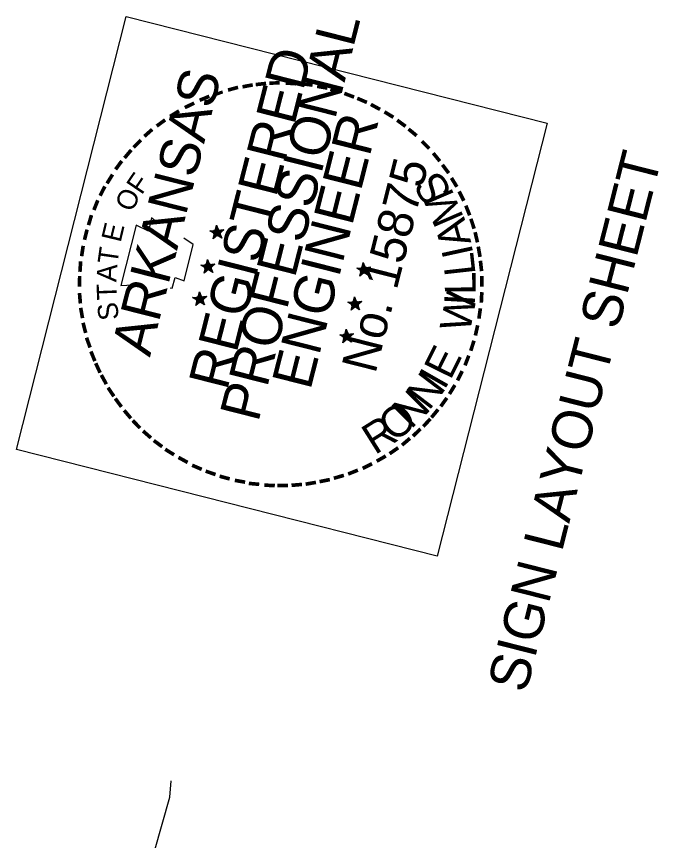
# Model space of a CAD drawing. Extents: x 670009 to 670131, y 737833 to 738002.
# Drawn here: x 670110.72 to 670130.78, y 737958.65 to 737984.38 of the extents above; entities that cross this region are included whole.
import ezdxf

# ---------------------------------------------------------------- set-up
doc = ezdxf.new("R2010")
doc.units = 0
for name, color, linetype in [('R_Border Notes', 7, 'Continuous'), ('R_Border PE', 7, 'Continuous'), ('R_Border Prem', 7, 'Continuous'), ('R_Exist Surface', 7, 'Continuous')]:
    doc.layers.add(name, color=color, linetype=linetype)

msp = doc.modelspace()

# ---------------------------------------------------------------- linework, layer by layer
at = {"layer": 'R_Border PE'}
for p, q in [((670116.97, 737977.859), (670116.935, 737977.668)), ((670116.97, 737977.859), (670116.956, 737977.676)), ((670116.97, 737977.859), (670116.968, 737977.673)), ((670116.97, 737977.859), (670116.983, 737977.63)), ((670116.97, 737977.859), (670116.991, 737977.712)), ((670116.97, 737977.859), (670116.999, 737977.716)), ((670116.97, 737977.859), (670117.008, 737977.727)), ((670116.765, 737977.685), (670116.927, 737977.689)), ((670116.983, 737977.63), (670116.765, 737977.685)), ((670116.765, 737977.685), (670116.924, 737977.677)), ((670116.765, 737977.685), (670116.914, 737977.661)), ((670116.765, 737977.685), (670116.913, 737977.635)), ((670116.765, 737977.685), (670116.91, 737977.623)), ((670116.765, 737977.685), (670116.901, 737977.612)), ((670116.863, 737977.435), (670116.983, 737977.63)), ((670116.863, 737977.435), (670116.921, 737977.588)), ((670116.863, 737977.435), (670116.931, 737977.579)), ((670116.863, 737977.435), (670116.938, 737977.577)), ((670116.863, 737977.435), (670116.96, 737977.565)), ((670116.863, 737977.435), (670116.972, 737977.562)), ((670116.863, 737977.435), (670116.984, 737977.559)), ((670117.131, 737977.451), (670116.98, 737977.566)), ((670117.197, 737977.711), (670116.983, 737977.63)), ((670117.131, 737977.451), (670116.983, 737977.63)), ((670117.131, 737977.451), (670117, 737977.568)), ((670117.197, 737977.711), (670117.002, 737977.677)), ((670117.197, 737977.711), (670117.005, 737977.689)), ((670117.131, 737977.451), (670117.009, 737977.578)), ((670117.197, 737977.711), (670117.024, 737977.665)), ((670117.197, 737977.711), (670117.032, 737977.618)), ((670117.131, 737977.451), (670117.032, 737977.618)), ((670117.131, 737977.451), (670117.032, 737977.592)), ((670117.197, 737977.711), (670117.044, 737977.64)), ((670117.197, 737977.711), (670117.05, 737977.613)), ((670117.131, 737977.451), (670117.051, 737977.619)), ((670116.692, 737976.788), (670116.657, 737976.597)), ((670116.692, 737976.788), (670116.678, 737976.605)), ((670116.692, 737976.788), (670116.69, 737976.602)), ((670116.692, 737976.788), (670116.705, 737976.559)), ((670116.692, 737976.788), (670116.713, 737976.641)), ((670116.692, 737976.788), (670116.722, 737976.652)), ((670116.692, 737976.788), (670116.73, 737976.656)), ((670116.481, 737976.616), (670116.649, 737976.619)), ((670116.705, 737976.559), (670116.481, 737976.616)), ((670116.481, 737976.616), (670116.64, 737976.608)), ((670116.481, 737976.616), (670116.636, 737976.59)), ((670116.481, 737976.616), (670116.629, 737976.566)), ((670116.481, 737976.616), (670116.632, 737976.552)), ((670116.481, 737976.616), (670116.625, 737976.547)), ((670116.585, 737976.364), (670116.705, 737976.559)), ((670116.585, 737976.364), (670116.637, 737976.519)), ((670116.585, 737976.364), (670116.649, 737976.515)), ((670116.921, 737976.646), (670116.705, 737976.559)), ((670116.855, 737976.386), (670116.705, 737976.559)), ((670116.921, 737976.646), (670116.721, 737976.62)), ((670116.921, 737976.646), (670116.724, 737976.606)), ((670116.921, 737976.646), (670116.746, 737976.594)), ((670116.921, 737976.646), (670116.754, 737976.547)), ((670116.855, 737976.386), (670116.754, 737976.547)), ((670116.855, 737976.386), (670116.754, 737976.521)), ((670116.921, 737976.646), (670116.766, 737976.57)), ((670116.921, 737976.646), (670116.772, 737976.542)), ((670116.855, 737976.386), (670116.773, 737976.548)), ((670121.569, 737976.467), (670121.351, 737976.522)), ((670121.351, 737976.522), (670121.512, 737976.52)), ((670121.351, 737976.522), (670121.51, 737976.514)), ((670121.351, 737976.522), (670121.506, 737976.496)), ((670121.351, 737976.522), (670121.5, 737976.472)), ((670121.351, 737976.522), (670121.496, 737976.46)), ((670121.351, 737976.522), (670121.493, 737976.447)), ((670121.555, 737976.69), (670121.521, 737976.505)), ((670121.555, 737976.69), (670121.542, 737976.512)), ((670121.555, 737976.69), (670121.554, 737976.509)), ((670121.555, 737976.69), (670121.569, 737976.467)), ((670121.555, 737976.69), (670121.576, 737976.543)), ((670121.555, 737976.69), (670121.591, 737976.552)), ((670121.555, 737976.69), (670121.598, 737976.556)), ((670121.783, 737976.548), (670121.569, 737976.467)), ((670121.783, 737976.548), (670121.586, 737976.508)), ((670121.783, 737976.548), (670121.589, 737976.52)), ((670121.783, 737976.548), (670121.615, 737976.494)), ((670121.783, 737976.548), (670121.622, 737976.447)), ((670121.783, 737976.548), (670121.628, 737976.471)), ((670121.783, 737976.548), (670121.64, 737976.442)), ((670116.585, 737976.364), (670116.66, 737976.506)), ((670116.585, 737976.364), (670116.682, 737976.494)), ((670116.585, 737976.364), (670116.694, 737976.491)), ((670116.585, 737976.364), (670116.706, 737976.488)), ((670116.855, 737976.386), (670116.702, 737976.496)), ((670116.855, 737976.386), (670116.722, 737976.497)), ((670116.855, 737976.386), (670116.731, 737976.508)), ((670121.449, 737976.272), (670121.569, 737976.467)), ((670121.449, 737976.272), (670121.505, 737976.419)), ((670121.449, 737976.272), (670121.518, 737976.416)), ((670121.449, 737976.272), (670121.528, 737976.406)), ((670121.449, 737976.272), (670121.546, 737976.402)), ((670121.449, 737976.272), (670121.563, 737976.391)), ((670121.449, 737976.272), (670121.575, 737976.388)), ((670121.717, 737976.288), (670121.564, 737976.397)), ((670121.717, 737976.288), (670121.569, 737976.467)), ((670121.717, 737976.288), (670121.59, 737976.397)), ((670121.717, 737976.288), (670121.601, 737976.414)), ((670121.717, 737976.288), (670121.618, 737976.429)), ((670121.717, 737976.288), (670121.622, 737976.447)), ((670121.717, 737976.288), (670121.636, 737976.45)), ((670116.436, 737975.776), (670116.4, 737975.586)), ((670116.436, 737975.776), (670116.421, 737975.593)), ((670116.436, 737975.776), (670116.434, 737975.59)), ((670116.436, 737975.776), (670116.449, 737975.548)), ((670116.436, 737975.776), (670116.456, 737975.629)), ((670116.436, 737975.776), (670116.466, 737975.64)), ((670116.436, 737975.776), (670116.473, 737975.644)), ((670116.224, 737975.604), (670116.393, 737975.607)), ((670116.449, 737975.548), (670116.224, 737975.604)), ((670116.224, 737975.604), (670116.384, 737975.596)), ((670116.224, 737975.604), (670116.38, 737975.584)), ((670116.224, 737975.604), (670116.374, 737975.56)), ((670116.224, 737975.604), (670116.376, 737975.54)), ((670116.224, 737975.604), (670116.368, 737975.536)), ((670116.328, 737975.352), (670116.449, 737975.548)), ((670116.328, 737975.352), (670116.38, 737975.507)), ((670116.328, 737975.352), (670116.392, 737975.504)), ((670116.328, 737975.352), (670116.403, 737975.495)), ((670116.328, 737975.352), (670116.427, 737975.488)), ((670116.664, 737975.635), (670116.449, 737975.548)), ((670116.598, 737975.374), (670116.449, 737975.548)), ((670116.664, 737975.635), (670116.464, 737975.608)), ((670116.664, 737975.635), (670116.467, 737975.594)), ((670116.598, 737975.374), (670116.474, 737975.496)), ((670116.664, 737975.635), (670116.49, 737975.582)), ((670116.664, 737975.635), (670116.497, 737975.535)), ((670116.598, 737975.374), (670116.497, 737975.535)), ((670116.598, 737975.374), (670116.497, 737975.509)), ((670116.664, 737975.635), (670116.509, 737975.558)), ((670116.664, 737975.635), (670116.515, 737975.531)), ((670116.598, 737975.374), (670116.517, 737975.537)), ((670121.277, 737975.619), (670121.243, 737975.434)), ((670121.277, 737975.619), (670121.264, 737975.442)), ((670121.277, 737975.619), (670121.276, 737975.439)), ((670121.277, 737975.619), (670121.291, 737975.396)), ((670121.277, 737975.619), (670121.298, 737975.472)), ((670121.277, 737975.619), (670121.307, 737975.482)), ((670121.277, 737975.619), (670121.322, 737975.492)), ((670116.328, 737975.352), (670116.438, 737975.479)), ((670116.328, 737975.352), (670116.45, 737975.476)), ((670116.598, 737975.374), (670116.445, 737975.484)), ((670116.598, 737975.374), (670116.465, 737975.485)), ((670121.291, 737975.396), (670121.073, 737975.451)), ((670121.073, 737975.451), (670121.234, 737975.449)), ((670121.073, 737975.451), (670121.232, 737975.443)), ((670121.073, 737975.451), (670121.228, 737975.425)), ((670121.073, 737975.451), (670121.221, 737975.401)), ((670121.073, 737975.451), (670121.218, 737975.389)), ((670121.073, 737975.451), (670121.209, 737975.378)), ((670121.171, 737975.201), (670121.291, 737975.396)), ((670121.171, 737975.201), (670121.227, 737975.348)), ((670121.171, 737975.201), (670121.239, 737975.345)), ((670121.171, 737975.201), (670121.246, 737975.343)), ((670121.171, 737975.201), (670121.268, 737975.331)), ((670121.171, 737975.201), (670121.28, 737975.328)), ((670121.171, 737975.201), (670121.292, 737975.325)), ((670121.439, 737975.217), (670121.288, 737975.332)), ((670121.505, 737975.477), (670121.291, 737975.396)), ((670121.439, 737975.217), (670121.291, 737975.396)), ((670121.505, 737975.477), (670121.308, 737975.437)), ((670121.505, 737975.477), (670121.313, 737975.455)), ((670121.439, 737975.217), (670121.314, 737975.332)), ((670121.439, 737975.217), (670121.323, 737975.343)), ((670121.505, 737975.477), (670121.332, 737975.431)), ((670121.439, 737975.217), (670121.34, 737975.384)), ((670121.439, 737975.217), (670121.34, 737975.358)), ((670121.505, 737975.477), (670121.346, 737975.382)), ((670121.505, 737975.477), (670121.35, 737975.4)), ((670121.505, 737975.477), (670121.356, 737975.373)), ((670121.439, 737975.217), (670121.358, 737975.379)), ((670121.022, 737974.613), (670120.986, 737974.422)), ((670121.022, 737974.613), (670121.007, 737974.43)), ((670121.022, 737974.613), (670121.02, 737974.427)), ((670121.022, 737974.613), (670121.035, 737974.384)), ((670121.022, 737974.613), (670121.041, 737974.46)), ((670121.022, 737974.613), (670121.05, 737974.471)), ((670121.022, 737974.613), (670121.065, 737974.48)), ((670121.249, 737974.466), (670121.035, 737974.384)), ((670121.249, 737974.466), (670121.051, 737974.425)), ((670121.249, 737974.466), (670121.056, 737974.443)), ((670121.249, 737974.466), (670121.076, 737974.419)), ((670121.249, 737974.466), (670121.089, 737974.371)), ((670121.249, 737974.466), (670121.094, 737974.389)), ((670121.249, 737974.466), (670121.1, 737974.361)), ((670120.817, 737974.44), (670120.979, 737974.444)), ((670121.035, 737974.384), (670120.817, 737974.44)), ((670120.817, 737974.44), (670120.976, 737974.432)), ((670120.817, 737974.44), (670120.971, 737974.413)), ((670120.817, 737974.44), (670120.965, 737974.389)), ((670120.817, 737974.44), (670120.962, 737974.377)), ((670120.817, 737974.44), (670120.953, 737974.367)), ((670120.914, 737974.189), (670121.035, 737974.384)), ((670120.914, 737974.189), (670120.972, 737974.342)), ((670120.914, 737974.189), (670120.983, 737974.333)), ((670120.914, 737974.189), (670120.989, 737974.332)), ((670120.914, 737974.189), (670121.012, 737974.319)), ((670120.914, 737974.189), (670121.024, 737974.316)), ((670120.914, 737974.189), (670121.036, 737974.313)), ((670121.183, 737974.205), (670121.031, 737974.321)), ((670121.183, 737974.205), (670121.035, 737974.384)), ((670121.183, 737974.205), (670121.057, 737974.321)), ((670121.183, 737974.205), (670121.066, 737974.331)), ((670121.183, 737974.205), (670121.083, 737974.372)), ((670121.183, 737974.205), (670121.083, 737974.346)), ((670121.183, 737974.205), (670121.101, 737974.368))]:
    msp.add_line(p, q, dxfattribs=at)
for points in [[(670115.082, 737977.964), (670114.934, 737978.092), (670114.84, 737977.671), (670114.463, 737977.863), (670113.985, 737975.979)], [(670116.765, 737977.685), (670117.197, 737977.711), (670116.863, 737977.435), (670116.97, 737977.859), (670117.131, 737977.451), (670116.765, 737977.685)], [(670115.527, 737975.904), (670115.581, 737975.89), (670115.679, 737976.226), (670115.956, 737976.124), (670116.244, 737977.257), (670115.953, 737977.459)], [(670116.481, 737976.616), (670116.921, 737976.646), (670116.585, 737976.364), (670116.692, 737976.788), (670116.855, 737976.386), (670116.481, 737976.616)], [(670121.351, 737976.522), (670121.783, 737976.548), (670121.449, 737976.272), (670121.555, 737976.69), (670121.717, 737976.288), (670121.351, 737976.522)], [(670113.985, 737975.979), (670114.528, 737976.009)], [(670116.224, 737975.604), (670116.664, 737975.635), (670116.328, 737975.352), (670116.436, 737975.776), (670116.598, 737975.374), (670116.224, 737975.604)], [(670121.073, 737975.451), (670121.505, 737975.477), (670121.171, 737975.201), (670121.277, 737975.619), (670121.439, 737975.217), (670121.073, 737975.451)], [(670120.817, 737974.44), (670121.249, 737974.466), (670120.914, 737974.189), (670121.022, 737974.613), (670121.183, 737974.205), (670120.817, 737974.44)]]:
    msp.add_lwpolyline(points, dxfattribs=at)
for centre, radius in [((670116.985, 737977.629), 0.108), ((670116.985, 737977.629), 0.0975), ((670116.985, 737977.629), 0.0904), ((670116.985, 737977.629), 0.083), ((670116.985, 737977.629), 0.0723), ((670116.985, 737977.629), 0.0672), ((670116.985, 737977.629), 0.0619), ((670116.985, 737977.629), 0.0533), ((670116.985, 737977.629), 0.0467), ((670116.985, 737977.629), 0.0388), ((670116.985, 737977.629), 0.031), ((670116.985, 737977.629), 0.0231), ((670116.985, 737977.629), 0.0185), ((670116.985, 737977.629), 0.00901), ((670116.706, 737976.56), 0.108), ((670116.706, 737976.56), 0.0975), ((670116.706, 737976.56), 0.0904), ((670116.706, 737976.56), 0.083), ((670116.706, 737976.56), 0.0723), ((670116.706, 737976.56), 0.0672), ((670116.706, 737976.56), 0.0619), ((670116.706, 737976.56), 0.0533), ((670116.706, 737976.56), 0.0467), ((670116.706, 737976.56), 0.0388), ((670116.706, 737976.56), 0.031), ((670116.706, 737976.56), 0.0231), ((670116.706, 737976.56), 0.0185), ((670116.706, 737976.56), 0.00901), ((670121.572, 737976.463), 0.108), ((670121.572, 737976.463), 0.0975), ((670121.572, 737976.463), 0.0904), ((670121.572, 737976.463), 0.083), ((670121.572, 737976.463), 0.0723), ((670121.572, 737976.463), 0.0672), ((670121.572, 737976.463), 0.0619), ((670121.572, 737976.463), 0.0533), ((670121.572, 737976.463), 0.0467), ((670121.572, 737976.463), 0.0388), ((670121.572, 737976.463), 0.031), ((670121.572, 737976.463), 0.0231), ((670121.572, 737976.463), 0.0185), ((670121.572, 737976.463), 0.00901), ((670116.45, 737975.549), 0.108), ((670116.45, 737975.549), 0.0975), ((670116.45, 737975.549), 0.0904), ((670116.45, 737975.549), 0.083), ((670116.45, 737975.549), 0.0723), ((670116.45, 737975.549), 0.0672), ((670116.45, 737975.549), 0.0619), ((670116.45, 737975.549), 0.0533), ((670116.45, 737975.549), 0.0467), ((670116.45, 737975.549), 0.0388), ((670116.45, 737975.549), 0.031), ((670116.45, 737975.549), 0.0231), ((670116.45, 737975.549), 0.0185), ((670116.45, 737975.549), 0.00901), ((670121.293, 737975.394), 0.108), ((670121.293, 737975.394), 0.0975), ((670121.293, 737975.394), 0.0904), ((670121.293, 737975.394), 0.083), ((670121.293, 737975.394), 0.0723), ((670121.293, 737975.394), 0.0672), ((670121.293, 737975.394), 0.0619), ((670121.293, 737975.394), 0.0533), ((670121.293, 737975.394), 0.0467), ((670121.293, 737975.394), 0.0388), ((670121.293, 737975.394), 0.031), ((670121.293, 737975.394), 0.0231), ((670121.293, 737975.394), 0.0185), ((670121.293, 737975.394), 0.00901), ((670121.037, 737974.383), 0.108), ((670121.037, 737974.383), 0.0975), ((670121.037, 737974.383), 0.0904), ((670121.037, 737974.383), 0.083), ((670121.037, 737974.383), 0.0723), ((670121.037, 737974.383), 0.0672), ((670121.037, 737974.383), 0.0619), ((670121.037, 737974.383), 0.0533), ((670121.037, 737974.383), 0.0467), ((670121.037, 737974.383), 0.0388), ((670121.037, 737974.383), 0.031), ((670121.037, 737974.383), 0.0231), ((670121.037, 737974.383), 0.0185), ((670121.037, 737974.383), 0.00901)]:
    msp.add_circle(centre, radius, dxfattribs=at)
at = {"layer": 'R_Border Prem'}
msp.add_lwpolyline([(670110.721, 737970.855), (670114.15, 737984.377), (670127.296, 737981.042), (670123.867, 737967.521)], close=True, dxfattribs=at)
at = {"layer": 'R_Exist Surface'}
msp.add_lwpolyline([(670113.381, 737952.482), (670115.507, 737959.994), (670115.557, 737960.504)], dxfattribs=at)

# ---------------------------------------------------------------- texts
at = {"layer": 'R_Border Notes'}
msp.add_text('SIGN LAYOUT SHEET', height=1.25, rotation=75.7686, dxfattribs=at).set_placement((670126.637, 737963.215))
at = {"layer": 'R_Border PE'}
for s, height, rotation, p in [('PROFESSIONAL', 1.24999, 75.7686, (670118.273, 737971.68)), ('REGISTERED', 1.25, 75.7686, (670117.298, 737972.669)), ('ARKANSAS', 1.25, 75.7686, (670114.889, 737973.719)), ('-', 1, 15.4369, (670117.374, 737981.69)), ('-', 1, 10.4313, (670117.793, 737981.79)), ('-', 1, 6.3414, (670118.178, 737981.86)), ('-', 1, 0.8918, (670118.565, 737981.91)), ('-', 1, 356.3179, (670119.05, 737981.916)), ('-', 1, 352.3647, (670119.537, 737981.902)), ('-', 1, 350.0987, (670119.988, 737981.826)), ('-', 1, 22.4207, (670116.535, 737981.38)), ('-', 0.875, 19.4438, (670116.956, 737981.59)), ('-', 1, 345.7092, (670120.375, 737981.748)), ('-', 1, 339.2857, (670120.771, 737981.634)), ('-', 1, 25.6483, (670116.092, 737981.157)), ('-', 1, 336.7638, (670121.16, 737981.49)), ('-', 1, 331.5312, (670121.555, 737981.319)), ('-', 1, 31.3471, (670115.671, 737980.897)), ('-', 1, 328.6366, (670121.964, 737981.1)), ('-', 1, 36.2983, (670115.282, 737980.608)), ('ENGINEER', 1.25, 75.7686, (670119.899, 737972.68)), ('-', 1, 323.6572, (670122.336, 737980.863)), ('-', 1, 41.6312, (670114.928, 737980.305)), ('-', 1, 320.3883, (670122.676, 737980.603)), ('-', 1, 45.4094, (670114.611, 737979.973)), ('-', 1, 314.8398, (670123.071, 737980.251)), ('-', 1, 49.8896, (670114.353, 737979.664)), ('-', 1, 309.6138, (670123.403, 737979.909)), ('-', 1, 53.6236, (670114.092, 737979.324)), ('No. 15875', 1.1, 75.7686, (670121.932, 737973.195)), ('-', 1, 307.0223, (670123.682, 737979.561)), ('-', 1, 58.1047, (670113.845, 737978.909)), ('F', 0.625, 55.8392, (670114.631, 737978.781)), ('S', 0.962, 121.462, (670124.355, 737978.882)), ('-', 1, 301.5339, (670123.948, 737979.184)), ('-', 1, 62.9734, (670113.651, 737978.552)), ('O', 0.625, 66.2201, (670114.346, 737978.241)), ('M', 0.962, 113.3256, (670124.707, 737978.093)), ('-', 1, 296.8536, (670124.177, 737978.791)), ('-', 1, 67.9303, (670113.474, 737978.133)), ('-', 1, 291.5049, (670124.377, 737978.385)), ('-', 1, 73.5116, (670113.324, 737977.694)), ('A', 0.962, 105.7601, (670124.931, 737977.32)), ('-', 1, 288.0176, (670124.53, 737977.998)), ('E', 0.625, 76.6009, (670113.972, 737977.298)), ('-', 1, 75.9548, (670113.206, 737977.253)), ('-', 1, 283.1254, (670124.658, 737977.611)), ('-', 1, 81.6654, (670113.13, 737976.776)), ('T', 0.625, 81.7913, (670113.869, 737976.614)), ('I', 0.962, 102.3343, (670124.999, 737976.962)), ('-', 1, 280.0202, (670124.755, 737977.181)), ('L', 0.962, 96.339, (670125.065, 737976.329)), ('-', 1, 85.9879, (670113.084, 737976.317)), ('A', 0.625, 86.9817, (670113.842, 737976.073)), ('-', 1, 276.487, (670124.823, 737976.764)), ('-', 1, 89.3987, (670113.077, 737975.88)), ('L', 0.962, 90.3438, (670125.065, 737975.691)), ('-', 1, 271.2428, (670124.866, 737976.321)), ('T', 0.625, 92.1721, (670113.865, 737975.532)), ('-', 1, 94.9446, (670113.107, 737975.389)), ('W', 0.962, 78.7816, (670124.878, 737974.478)), ('-', 1, 267.0543, (670124.875, 737975.848)), ('I', 0.962, 86.9179, (670125.035, 737975.328)), ('-', 1, 100.0758, (670113.174, 737974.966)), ('S', 0.625, 97.3626, (670113.926, 737974.93)), ('-', 1, 261.5852, (670124.84, 737975.379)), ('-', 1, 104.5604, (670113.271, 737974.535)), ('-', 1, 257.3603, (670124.764, 737974.876)), ('-', 1, 109.8321, (670113.403, 737974.115)), ('-', 1, 252.2868, (670124.662, 737974.425)), ('E', 0.962, 63.7221, (670124.277, 737972.998)), ('-', 1, 112.0003, (670113.55, 737973.704)), ('-', 1, 248.884, (670124.511, 737973.98)), ('-', 1, 114.7192, (670113.708, 737973.36)), ('-', 1, 118.7308, (670113.895, 737973.029)), ('N', 0.962, 52.7308, (670123.605, 737972.044)), ('I', 0.962, 60.2962, (670124.087, 737972.687)), ('-', 1, 243.3241, (670124.326, 737973.53)), ('-', 1, 124.1916, (670114.117, 737972.683)), ('N', 0.962, 45.1654, (670123.043, 737971.469)), ('-', 1, 238.5668, (670124.118, 737973.119)), ('-', 1, 126.3827, (670114.346, 737972.367)), ('-', 1, 234.3298, (670123.886, 737972.739)), ('O', 0.962, 38.8847, (670122.522, 737971.052)), ('-', 1, 230.3687, (670123.632, 737972.397)), ('-', 1, 130.001, (670114.628, 737972.031)), ('-', 1, 133.8392, (670114.899, 737971.75)), ('R', 0.962, 32.1757, (670121.918, 737970.672)), ('-', 1, 227.3389, (670123.407, 737972.119)), ('-', 1, 138.6399, (670115.22, 737971.468)), ('-', 1, 223.8583, (670123.118, 737971.819)), ('-', 1, 143.5428, (670115.55, 737971.217)), ('-', 1, 220.4149, (670122.808, 737971.536)), ('-', 1, 148.163, (670115.898, 737970.987)), ('-', 1, 214.7024, (670122.473, 737971.26)), ('-', 1, 151.2295, (670116.305, 737970.761)), ('-', 1, 209.9924, (670122.115, 737971.016)), ('-', 1, 156.9698, (670116.714, 737970.567)), ('-', 1, 206.4867, (670121.708, 737970.783)), ('-', 1, 160.9549, (670117.121, 737970.419)), ('-', 1, 196.2157, (670120.897, 737970.435)), ('-', 1, 201.662, (670121.298, 737970.591)), ('-', 1, 164.8308, (670117.54, 737970.293)), ('-', 1, 169.9644, (670117.989, 737970.205)), ('-', 1, 174.7165, (670118.399, 737970.146)), ('-', 1, 189.8329, (670120.068, 737970.219)), ('-', 1, 191.4974, (670120.49, 737970.306)), ('-', 1, 177.4835, (670118.868, 737970.111)), ('-', 1, 181.2264, (670119.251, 737970.123)), ('-', 1, 184.856, (670119.665, 737970.154))]:
    msp.add_text(s, height=height, rotation=rotation, dxfattribs=at).set_placement(p)

doc.saveas('drawing.dxf')
